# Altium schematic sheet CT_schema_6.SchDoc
size 430 x 414 mm
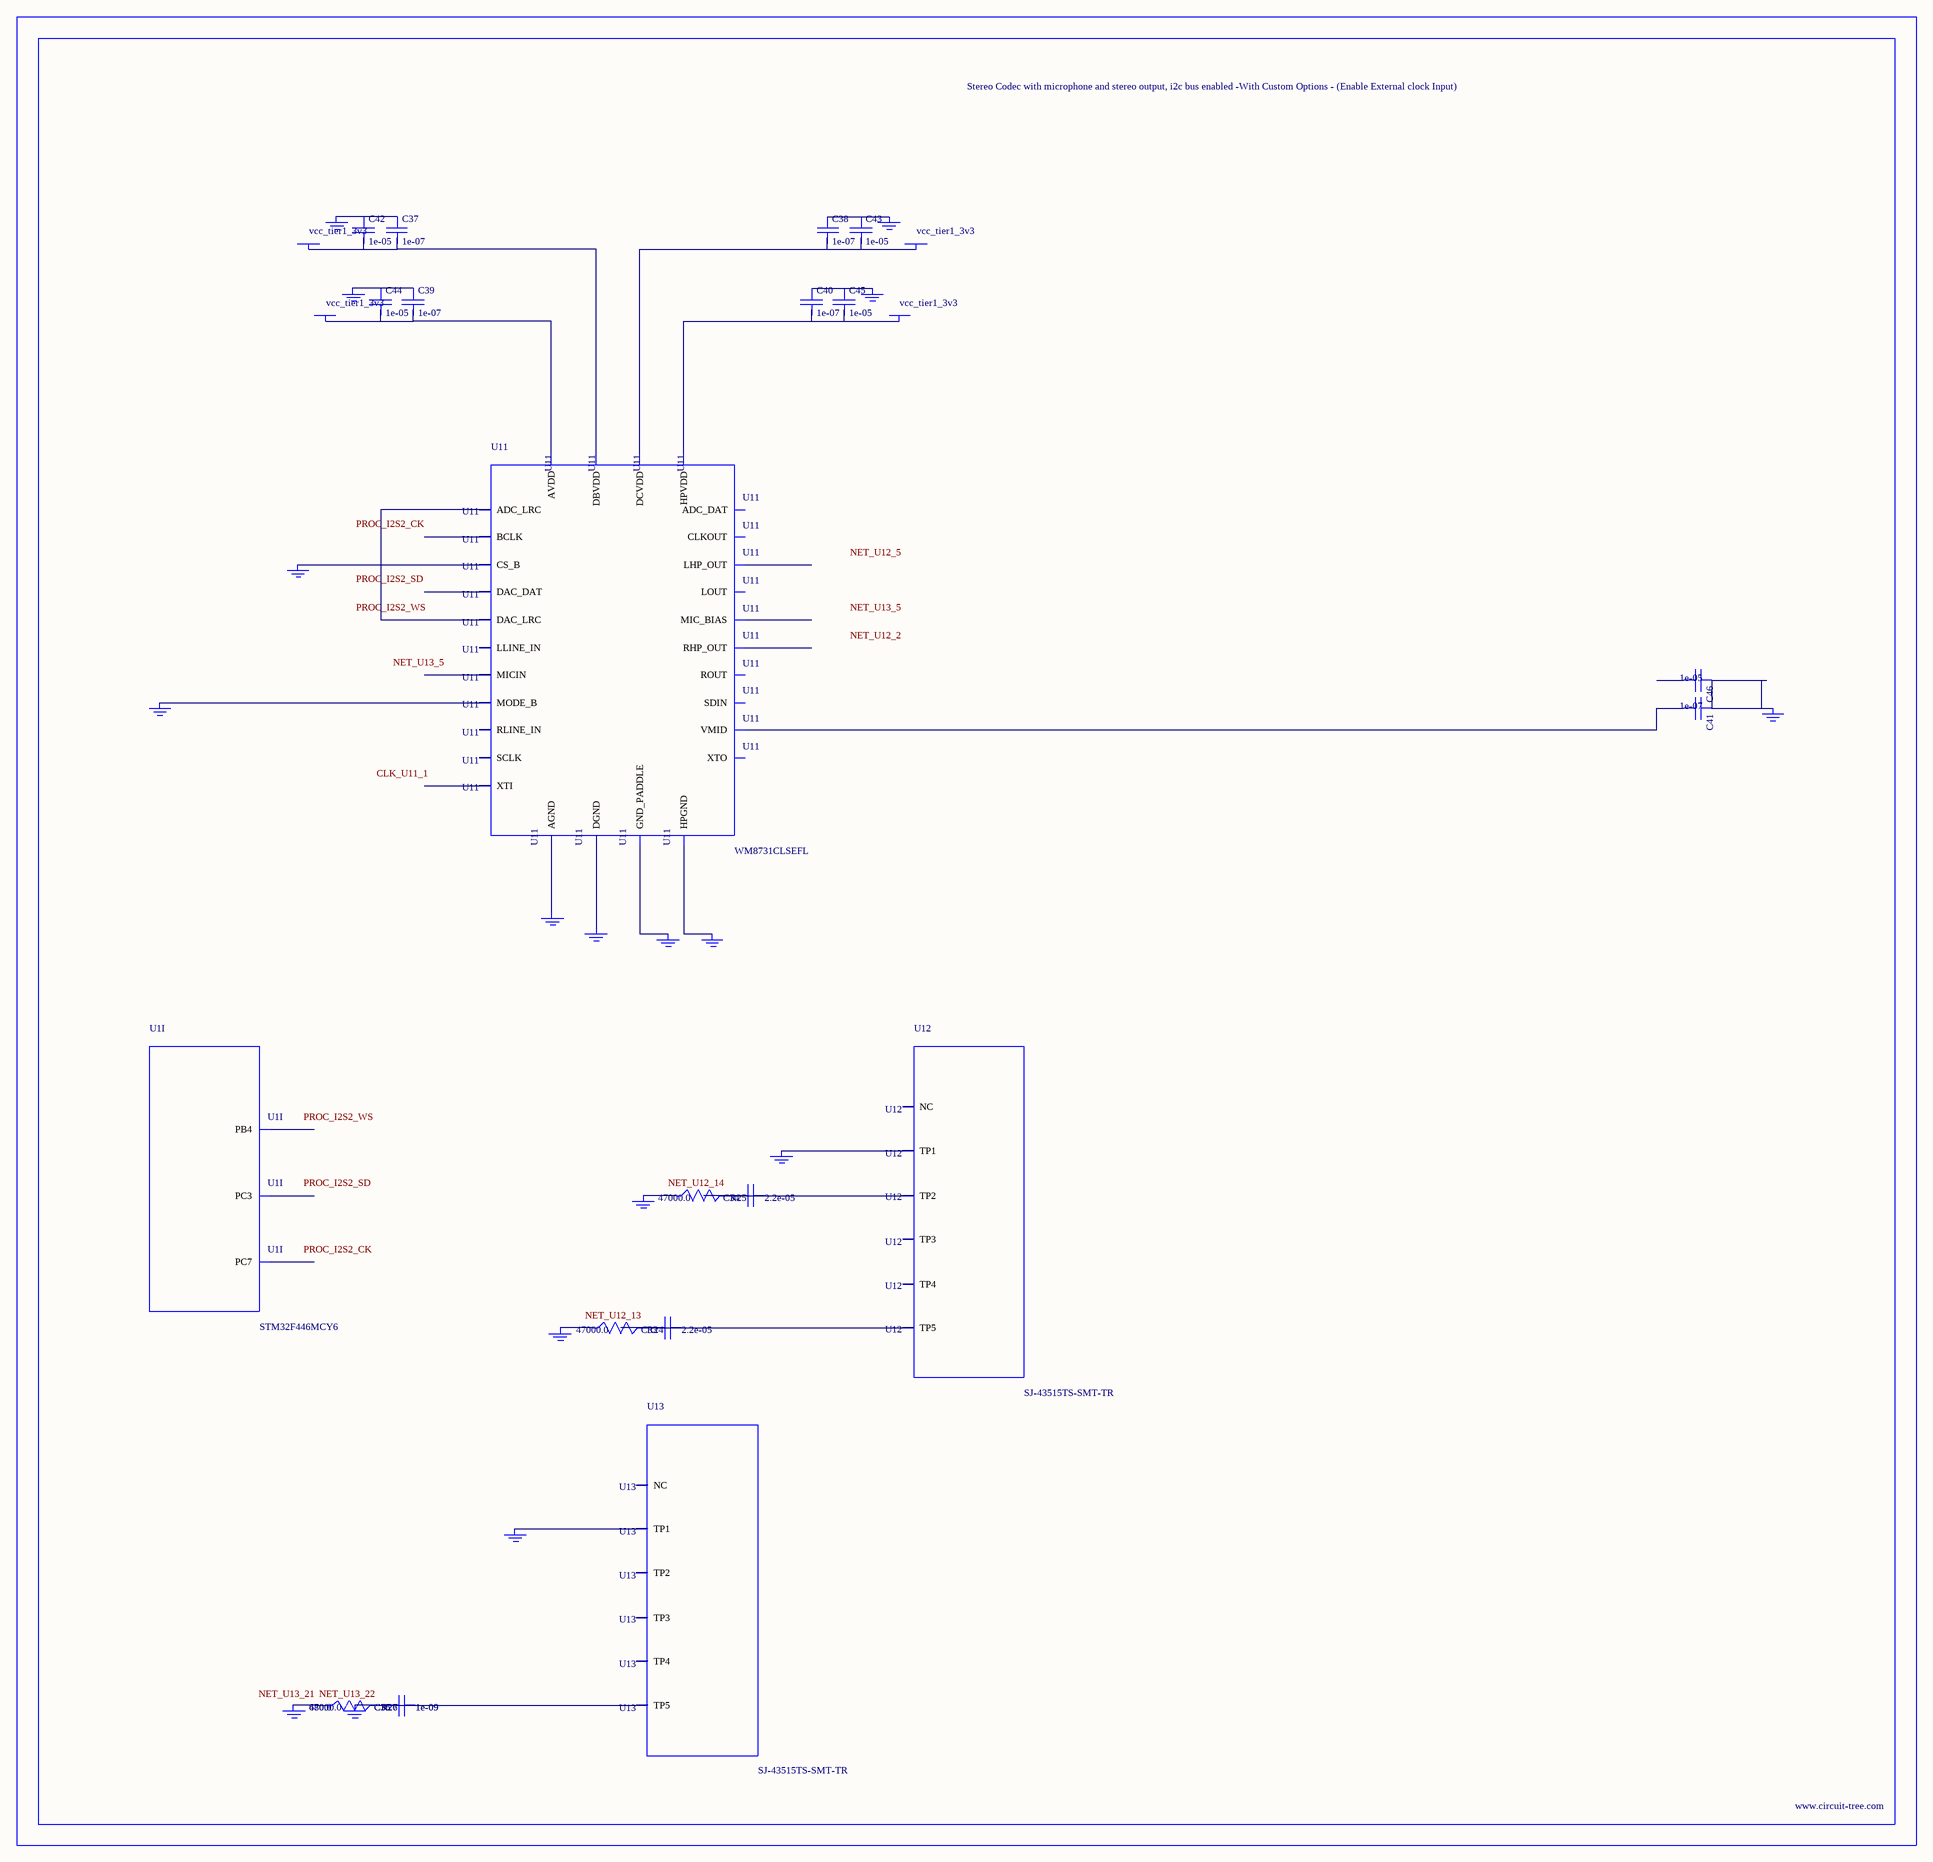
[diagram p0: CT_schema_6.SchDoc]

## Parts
BORDER5  (no value)
C33  2.2e-05  [C1210]
C34  2.2e-05  [C1210]
C35  1e-09  [C0402]
C36  1e-09  [C0402]
C37  1e-07  [C0402]
C38  1e-07  [C0402]
C39  1e-07  [C0402]
C40  1e-07  [C0402]
C41  1e-07  [C0402]
C42  1e-05  [C0805]
C43  1e-05  [C0805]
C44  1e-05  [C0805]
C45  1e-05  [C0805]
C46  1e-05  [C0805]
GND_INSTANCE_5_0  (no value)
GND_INSTANCE_5_1  (no value)
GND_INSTANCE_5_2  (no value)
GND_INSTANCE_5_3  (no value)
GND_INSTANCE_5_4  (no value)
GND_INSTANCE_5_5  (no value)
GND_INSTANCE_5_6  (no value)
GND_INSTANCE_5_7  (no value)
GND_INSTANCE_5_8  (no value)
GND_INSTANCE_5_9  (no value)
GND_INSTANCE_5_10  (no value)
GND_INSTANCE_5_11  (no value)
GND_INSTANCE_5_12  (no value)
GND_INSTANCE_5_13  (no value)
GND_INSTANCE_5_14  (no value)
GND_INSTANCE_5_15  (no value)
GND_INSTANCE_5_16  (no value)
POWER_INSTANCE_5_0  vcc_tier1_3v3
POWER_INSTANCE_5_1  vcc_tier1_3v3
POWER_INSTANCE_5_2  vcc_tier1_3v3
POWER_INSTANCE_5_3  vcc_tier1_3v3
R24  47000.0  [R0603]
R25  47000.0  [R0603]
R26  47000.0  [R0603]
R27  680.0  [R0603]
U1  STM32F446MCY6  [WLCSP81]  (part I of 9)
U11  WM8731CLSEFL  [QFN-28]
U12  SJ-43515TS-SMT-TR  [SJ-43515TS-SMT-TR]
U13  SJ-43515TS-SMT-TR  [SJ-43515TS-SMT-TR]

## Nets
NetC33_1: C33.1 C33.2 R24.2 U12.5(TP5)
NetC34_1: C34.1 C34.2 R25.2 U12.2(TP2)
NetC35_1: C35.1 C35.2 C36.1 C36.2 GND_INSTANCE_5_16.0(GND) R26.2 R27.2 U13.5(TP5)
NetC37_1: C37.1 C42.1 GND_INSTANCE_5_1.0(GND)
NetC37_2: C37.2 C42.2 POWER_INSTANCE_5_1.0(PWR) U11.5(DBVDD)
NetC38_1: C38.1 C43.1 GND_INSTANCE_5_0.0(GND)
NetC38_2: C38.2 C43.2 POWER_INSTANCE_5_0.0(PWR) U11.3(DCVDD)
NetC39_1: C39.1 C44.1 GND_INSTANCE_5_4.0(GND)
NetC39_2: C39.2 C44.2 POWER_INSTANCE_5_3.0(PWR) U11.18(AVDD)
NetC40_1: C40.1 C45.1 GND_INSTANCE_5_2.0(GND)
NetC40_2: C40.2 C45.2 POWER_INSTANCE_5_2.0(PWR) U11.12(HPVDD)
NetC41_1: C41.1 C46.1 GND_INSTANCE_5_5.0(GND)
NetC41_2: C41.2 U11.20(VMID)
NetGND_INSTANCE_5_3_0: GND_INSTANCE_5_3.0(GND) U11.15(HPGND)
NetGND_INSTANCE_5_6_0: GND_INSTANCE_5_6.0(GND) U11.25(MODE_B)
NetGND_INSTANCE_5_7_0: GND_INSTANCE_5_7.0(GND) U11.26(CS_B)
NetGND_INSTANCE_5_8_0: GND_INSTANCE_5_8.0(GND) U11.29(GND_PADDLE)
NetGND_INSTANCE_5_9_0: GND_INSTANCE_5_9.0(GND) U11.4(DGND)
NetGND_INSTANCE_5_10_0: GND_INSTANCE_5_10.0(GND) U11.19(AGND)
NetGND_INSTANCE_5_11_0: GND_INSTANCE_5_11.0(GND) U12.1(TP1)
NetGND_INSTANCE_5_12_0: GND_INSTANCE_5_12.0(GND) R25.1
NetGND_INSTANCE_5_13_0: GND_INSTANCE_5_13.0(GND) R24.1
NetGND_INSTANCE_5_14_0: GND_INSTANCE_5_14.0(GND) U13.1(TP1)
NetGND_INSTANCE_5_15_0: GND_INSTANCE_5_15.0(GND) R26.1 R27.1
NetU11_9: U11.9(DAC_LRC) U11.11(ADC_LRC)

Not connected (* = marked no-connect by the designer): C46 2; U1 B5(PB4) F2(PC7) F8(PC3); U11 1(XTI) 2(XTO) 6(CLKOUT) 7(BCLK) 8(DAC_DAT) 10(ADC_DAT) 13(LHP_OUT) 14(RHP_OUT) 16(LOUT) 17(ROUT) 21(MIC_BIAS) 22(MICIN) 23(RLINE_IN) 24(LLINE_IN) 27(SDIN) 28(SCLK); U12 3(TP3) 4(TP4) 6(NC); U13 2(TP2) 3(TP3) 4(TP4) 6(NC)

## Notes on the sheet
- Labels drawn without touching a wire or pin: CLK_U11_1, NET_U12_2, NET_U12_5, NET_U12_13, NET_U12_14, NET_U13_5, NET_U13_21, NET_U13_22, PROC_I2S2_CK, PROC_I2S2_SD, PROC_I2S2_WS

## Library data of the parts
BORDER5 = BORDER_PAGE5
C33 C34 = C1210C224K5RACTU
C35 C36 = C0402C102K3RAC
C37-C41 = C0402C104K3RACTU
C42-C46 = C0805C106K8RACTU
GND_INSTANCE_5_0-GND_INSTANCE_5_16 = GND
POWER_INSTANCE_5_0-POWER_INSTANCE_5_3 = PWR
R24-R26 = RC0603JR-0747KL
R27 = RC0603JR-07680RL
